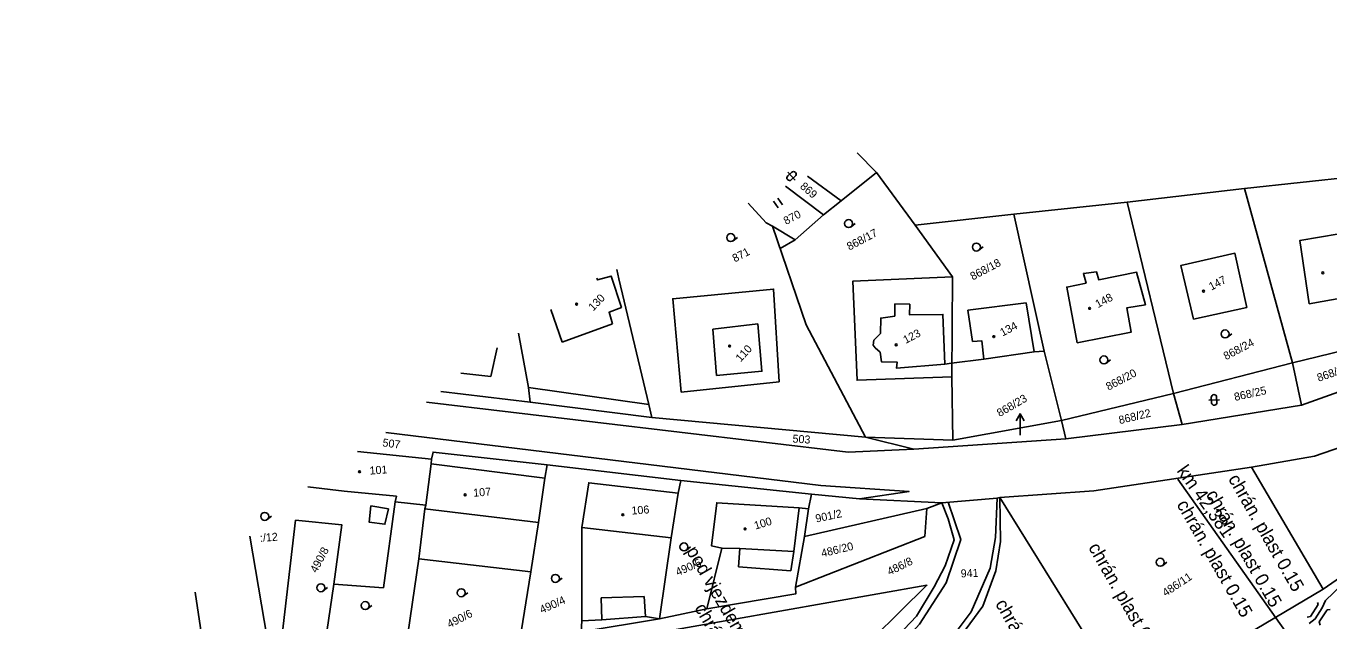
# Model space of a CAD drawing. Extents: x -514509 to -512782, y -1144610 to -1143439.
# Drawn here: x -513652.6 to -513408.3, y -1143676 to -1143564.4 of the extents above; entities that cross this region are included whole.
import ezdxf

# ---------------------------------------------------------------- set-up
doc = ezdxf.new("R2010")
doc.units = 0
for name, color, linetype in [('Vrstva 1', 7, 'Continuous'), ('Vrstva 10', 7, 'Continuous'), ('Vrstva 25', 7, 'Continuous'), ('Vrstva 61', 7, 'Continuous'), ('Vrstva 62', 7, 'Continuous'), ('Vrstva 8', 7, 'Continuous'), ('Vrstva 9', 7, 'Continuous')]:
    doc.layers.add(name, color=color, linetype=linetype)

msp = doc.modelspace()

# ---------------------------------------------------------------- linework, layer by layer
at = {"layer": 'Vrstva 1'}
msp.add_lwpolyline([(-513412.036, -1143676.539), (-513410.908, -1143675.642), (-513409.638, -1143673.559), (-513409.022, -1143672.206), (-513406.01, -1143669.345)], dxfattribs=at)
at = {"layer": 'Vrstva 10'}
msp.add_lwpolyline([(-513582.696, -1143761.24), (-513581.966, -1143752.218), (-513543.007, -1143722.265), (-513536.98, -1143726.125), (-513503.11, -1143701.59), (-513467.163, -1143704.368), (-513409.406, -1143670.068), (-513367.763, -1143641.182), (-513337.875, -1143622.14), (-513302.677, -1143606.244), (-513297.569, -1143595.846), (-513289.461, -1143596.696), (-513287.694, -1143584.666), (-513262.147, -1143588.316), (-513251.067, -1143584.844), (-513248.39, -1143579.25), (-513218.784, -1143572.229), (-513191.434, -1143567.629), (-513154.1, -1143564.42), (-513082.649, -1143574.448)], dxfattribs=at)
msp.add_lwpolyline([(-513582.696, -1143761.24), (-513581.966, -1143752.218), (-513543.007, -1143722.265), (-513536.98, -1143726.125), (-513503.11, -1143701.59), (-513467.163, -1143704.368), (-513409.406, -1143670.068), (-513367.763, -1143641.182), (-513337.875, -1143622.14), (-513302.677, -1143606.244), (-513297.569, -1143595.846), (-513289.461, -1143596.696), (-513287.694, -1143584.666), (-513262.147, -1143588.316), (-513251.067, -1143584.844), (-513248.39, -1143579.25), (-513218.784, -1143572.229), (-513191.434, -1143567.629), (-513154.1, -1143564.42), (-513082.649, -1143574.448)], dxfattribs=at)
for points in [[(-513313.028, -1143634.411), (-513303.623, -1143630.921), (-513298.925, -1143628.763), (-513296.747, -1143627.462), (-513295.945, -1143626.166), (-513295.554, -1143624.532), (-513295.924, -1143622.761), (-513296.628, -1143622.04), (-513297.564, -1143622.144), (-513299.651, -1143622.875), (-513306.089, -1143625.417), (-513313.165, -1143628.458), (-513321.801, -1143632.456), (-513331.249, -1143637.407), (-513340.422, -1143642.868), (-513349.401, -1143648.415), (-513353.369, -1143652.099), (-513356.695, -1143655.538), (-513359.416, -1143658.705), (-513362.379, -1143661.416), (-513365.213, -1143663.797), (-513369.131, -1143666.807), (-513372.727, -1143669.506), (-513383.146, -1143676.5), (-513393.468, -1143683.537), (-513398.042, -1143686.718), (-513405.384, -1143691.933), (-513410.151, -1143695.762), (-513415.154, -1143699.922), (-513418.131, -1143702.84), (-513423.071, -1143706.989), (-513430.088, -1143713.017)], [(-513435.79, -1143720.105), (-513422.696, -1143709.16), (-513412.424, -1143700.068), (-513405.215, -1143694.088), (-513397.354, -1143688.38), (-513386.063, -1143680.692), (-513374.141, -1143672.521), (-513366.016, -1143666.699), (-513361.881, -1143663.312), (-513358.552, -1143660.3), (-513355.953, -1143657.514), (-513352.811, -1143654.119), (-513350.492, -1143651.614), (-513348.384, -1143649.644), (-513345.759, -1143647.798), (-513339.616, -1143643.857), (-513326.377, -1143636.333), (-513315.497, -1143630.928), (-513306.602, -1143627.259), (-513301.474, -1143625.525)], [(-513411.988, -1143704.704), (-513402.55, -1143697.523), (-513392.088, -1143689.804), (-513385.47, -1143685.32), (-513382.766, -1143683.684), (-513373.999, -1143679.047), (-513366.674, -1143674.561), (-513360.563, -1143670.218), (-513355.795, -1143665.131), (-513348.391, -1143656.829), (-513341.216, -1143651.53), (-513334.333, -1143646.865), (-513323.242, -1143640.123), (-513316.692, -1143635.986), (-513314.355, -1143634.999)]]:
    msp.add_spline(points, degree=3, dxfattribs=at)
at = {"layer": 'Vrstva 25'}
msp.add_lwpolyline([(-513436.662, -1143649.403), (-513415.746, -1143679.07)], dxfattribs=at)
at = {"layer": 'Vrstva 61'}
for points in [[(-513412.442, -1143675.308), (-513411.824, -1143675.194), (-513410.36, -1143672.938)], [(-513410.36, -1143672.938), (-513410.463, -1143672.558)], [(-513408.699, -1143673.926), (-513410.157, -1143676.216), (-513410.015, -1143676.829)], [(-513408.097, -1143673.862), (-513408.699, -1143673.926)]]:
    msp.add_lwpolyline(points, dxfattribs=at)
at = {"layer": 'Vrstva 8'}
for p, q in [((-513496.813, -1143588.219), (-513493.199, -1143591.919)), ((-513506.131, -1143592.588), (-513499.789, -1143597.189)), ((-513503.084, -1143599.824), (-513510.199, -1143594.48)), ((-513424.194, -1143594.886), (-513415.173, -1143627.584)), ((-513512.666, -1143601.956), (-513508.41, -1143604.514)), ((-513489.755, -1143616.528), (-513486.929, -1143616.584)), ((-513476.067, -1143617.711), (-513465.107, -1143616.372)), ((-513465.107, -1143616.372), (-513463.62, -1143625.531)), ((-513552.076, -1143623.724), (-513554.237, -1143617.582)), ((-513542.69, -1143620.298), (-513552.076, -1143623.724)), ((-513523.833, -1143621.299), (-513515.396, -1143620.27)), ((-513415.173, -1143627.584), (-513413.496, -1143635.563)), ((-513558.398, -1143632.231), (-513535.869, -1143635.399)), ((-513458.472, -1143638.442), (-513457.653, -1143641.833)), ((-513576.62, -1143645.693), (-513590.455, -1143644.269)), ((-513576.63, -1143646.545), (-513555.337, -1143649.273)), ((-513583.419, -1143653.702), (-513577.671, -1143654.306)), ((-513584.673, -1143654.966), (-513587.964, -1143654.446)), ((-513577.832, -1143654.976), (-513556.52, -1143657.535)), ((-513548.403, -1143658.526), (-513531.65, -1143660.464)), ((-513508.339, -1143669.664), (-513506.675, -1143660.162)), ((-513518.81, -1143662.466), (-513508.658, -1143663.024)), ((-513519.01, -1143665.861), (-513509.226, -1143666.645)), ((-513544.797, -1143671.724), (-513536.698, -1143671.435)), ((-513544.681, -1143675.792), (-513544.797, -1143671.724)), ((-513536.698, -1143671.435), (-513536.469, -1143675.171)), ((-513536.469, -1143675.171), (-513544.681, -1143675.792)), ((-513481.481, -1143682.388), (-513475.438, -1143674.345))]:
    msp.add_line(p, q, dxfattribs=at)
for points in [[(-513485.907, -1143601.797), (-513493.199, -1143591.919), (-513499.789, -1143597.189), (-513503.084, -1143599.824), (-513508.41, -1143604.514), (-513511.234, -1143606.136)], [(-513403.286, -1143592.638), (-513424.194, -1143594.886), (-513446.168, -1143597.475), (-513467.416, -1143599.696), (-513485.907, -1143601.797), (-513478.935, -1143611.479), (-513479.065, -1143630.227), (-513478.852, -1143642.096), (-513458.472, -1143638.442), (-513437.507, -1143633.384), (-513415.173, -1143627.584), (-513393.849, -1143622.385)], [(-513478.852, -1143642.096), (-513495.247, -1143641.551), (-513506.339, -1143620.454), (-513512.666, -1143601.956), (-513513.883, -1143601.347), (-513517.242, -1143597.667)], [(-513435.839, -1143639.146), (-513437.507, -1143633.384), (-513446.168, -1143597.475)], [(-513458.472, -1143638.442), (-513461.724, -1143625.391), (-513467.416, -1143599.696)], [(-513422.854, -1143647.177), (-513411.055, -1143645.138), (-513373.068, -1143631.979), (-513339.412, -1143613.869), (-513313.432, -1143600.771), (-513322.783, -1143615.321)], [(-513535.285, -1143637.833), (-513535.869, -1143635.399), (-513541.458, -1143611.844), (-513541.863, -1143610.106)], [(-513545.612, -1143611.707), (-513545.479, -1143612.058), (-513542.91, -1143611.326), (-513540.978, -1143617.195), (-513543.31, -1143618.117), (-513542.69, -1143620.298)], [(-513479.065, -1143630.227), (-513496.818, -1143630.885), (-513497.619, -1143612.315), (-513478.935, -1143611.479)], [(-513461.724, -1143625.391), (-513463.62, -1143625.531), (-513473.039, -1143626.908), (-513479.133, -1143627.698), (-513480.352, -1143627.856), (-513489.442, -1143628.577), (-513489.322, -1143627.478), (-513492.233, -1143627.415), (-513492.464, -1143625.606), (-513493.402, -1143624.763), (-513493.781, -1143624.306), (-513493.679, -1143623.376), (-513492.425, -1143622.112), (-513492.366, -1143619.218), (-513489.749, -1143618.831), (-513489.755, -1143616.528)], [(-513486.929, -1143616.584), (-513486.98, -1143618.626), (-513480.705, -1143618.533), (-513480.352, -1143627.856)], [(-513473.039, -1143626.908), (-513473.435, -1143623.465), (-513475.164, -1143623.582), (-513476.067, -1143617.711)], [(-513558.107, -1143634.982), (-513558.398, -1143632.231), (-513560.254, -1143622.02)], [(-513515.396, -1143620.27), (-513514.656, -1143629.199), (-513523.151, -1143629.967), (-513523.833, -1143621.299)], [(-513571.078, -1143629.534), (-513565.481, -1143630.154), (-513564.294, -1143624.791)], [(-513577.56, -1143634.96), (-513498.476, -1143644.362), (-513486.158, -1143643.813), (-513457.653, -1143641.833), (-513435.839, -1143639.146), (-513413.496, -1143635.563), (-513391.444, -1143627.693)], [(-513486.158, -1143643.813), (-513495.247, -1143641.551), (-513535.285, -1143637.833), (-513558.107, -1143634.982), (-513574.85, -1143632.96)], [(-513496.375, -1143653.142), (-513487.048, -1143651.757), (-513503.632, -1143650.6), (-513585.141, -1143640.662)], [(-513578.968, -1143664.349), (-513577.832, -1143654.976), (-513577.671, -1143654.306), (-513576.63, -1143646.545), (-513576.62, -1143645.693), (-513576.299, -1143644.355), (-513554.883, -1143646.752), (-513529.843, -1143649.695), (-513505.36, -1143652.252), (-513496.375, -1143653.142), (-513480.942, -1143653.866), (-513470.559, -1143652.992)], [(-513557.986, -1143666.797), (-513556.52, -1143657.535), (-513555.337, -1143649.273), (-513554.883, -1143646.752)], [(-513470.031, -1143652.864), (-513452.408, -1143651.632), (-513422.854, -1143647.177), (-513409.406, -1143670.068)], [(-513583.129, -1143652.617), (-513592.979, -1143651.656), (-513599.758, -1143650.857)], [(-513548.39, -1143676.007), (-513548.403, -1143658.526), (-513547.116, -1143650.102), (-513530.363, -1143652.041)], [(-513529.843, -1143649.695), (-513530.363, -1143652.041), (-513531.65, -1143660.464), (-513533.864, -1143675.635), (-513536.469, -1143675.171)], [(-513594.93, -1143669.125), (-513585.611, -1143669.815), (-513583.419, -1143653.702), (-513583.129, -1143652.617)], [(-513492.629, -1143682.433), (-513485.641, -1143675.148), (-513482.364, -1143669.612), (-513480.295, -1143665.685), (-513478.632, -1143660.787), (-513479.735, -1143656.862), (-513480.942, -1143653.866), (-513483.718, -1143654.923), (-513484.135, -1143660.176), (-513508.339, -1143669.664), (-513508.312, -1143670.945), (-513525, -1143673.787), (-513533.864, -1143675.635), (-513548.533, -1143678.042)], [(-513525, -1143673.787), (-513522.146, -1143662.369), (-513524.075, -1143661.958), (-513523.103, -1143653.849), (-513507.676, -1143654.831), (-513505.927, -1143655.021)], [(-513483.718, -1143654.923), (-513506.675, -1143660.162), (-513505.927, -1143655.021), (-513505.36, -1143652.252)], [(-513479.738, -1143653.763), (-513477.339, -1143660.72), (-513480.136, -1143668.853), (-513485.123, -1143676.639), (-513491.478, -1143683.634), (-513495.386, -1143687.158)], [(-513446.005, -1143691.624), (-513470.031, -1143652.864), (-513469.93, -1143661.143), (-513470.8, -1143666.616), (-513473.257, -1143673.241), (-513480.547, -1143683.23), (-513486.741, -1143689.555), (-513493.388, -1143694.566), (-513487.156, -1143688.669), (-513481.481, -1143682.388)], [(-513475.438, -1143674.345), (-513471.857, -1143666.105), (-513470.874, -1143660.385), (-513470.559, -1143652.992), (-513470.031, -1143652.864)], [(-513587.964, -1143654.446), (-513588.296, -1143657.49), (-513585.337, -1143657.898), (-513584.673, -1143654.966)], [(-513509.226, -1143666.645), (-513508.658, -1143663.024), (-513507.676, -1143654.831)], [(-513605.792, -1143688.805), (-513602.071, -1143657.127), (-513593.426, -1143657.99), (-513594.93, -1143669.125), (-513597.533, -1143686.993)], [(-513605.792, -1143688.805), (-513610.633, -1143660.108)], [(-513522.146, -1143662.369), (-513518.81, -1143662.466), (-513519.01, -1143665.861)], [(-513581.863, -1143684.07), (-513578.968, -1143664.349), (-513557.986, -1143666.797), (-513560.068, -1143680.017)], [(-513661.135, -1143698.528), (-513647.306, -1143695.968), (-513617.922, -1143690.733), (-513620.897, -1143670.627)], [(-513538.877, -1143679.071), (-513483.704, -1143669.334), (-513513.863, -1143699.065), (-513532.594, -1143713.255)], [(-513544.681, -1143675.792), (-513548.39, -1143676.007), (-513548.533, -1143678.042)]]:
    msp.add_lwpolyline(points, dxfattribs=at)
for points in [[(-513412.086, -1143616.531), (-513413.788, -1143604.626), (-513402.772, -1143602.781), (-513401.231, -1143614.588)], [(-513433.769, -1143619.397), (-513436.1, -1143609.318), (-513425.983, -1143607.059), (-513423.747, -1143617.216)], [(-513455.543, -1143623.876), (-513457.487, -1143613.402), (-513453.888, -1143612.667), (-513454.374, -1143610.837), (-513451.937, -1143610.521), (-513451.498, -1143612.006), (-513444.395, -1143610.614), (-513442.745, -1143616.716), (-513446.24, -1143617.289), (-513445.454, -1143621.871)], [(-513529.759, -1143633.104), (-513531.36, -1143615.579), (-513512.453, -1143613.769), (-513511.438, -1143631.162)]]:
    msp.add_lwpolyline(points, close=True, dxfattribs=at)
at = {"layer": 'Vrstva 9'}
for p, q in [((-513509.06, -1143591.863), (-513509.807, -1143592.528)), ((-513509.767, -1143591.825), (-513508.436, -1143593.316)), ((-513508.395, -1143592.611), (-513509.142, -1143593.276)), ((-513512.471, -1143597.274), (-513511.631, -1143598.517)), ((-513510.803, -1143597.957), (-513511.642, -1143596.713)), ((-513497.946, -1143602.068), (-513497.155, -1143601.458)), ((-513520.04, -1143604.708), (-513519.249, -1143604.098)), ((-513473.982, -1143606.474), (-513473.191, -1143605.864)), ((-513427.346, -1143622.774), (-513426.555, -1143622.164)), ((-513450.084, -1143627.663), (-513449.293, -1143627.053)), ((-513430.874, -1143634.612), (-513428.876, -1143634.517)), ((-513430.399, -1143634.087), (-513430.352, -1143635.086)), ((-513429.399, -1143634.041), (-513429.353, -1143635.04)), ((-513466.998, -1143638.459), (-513466.248, -1143637.159)), ((-513607.405, -1143657.013), (-513606.614, -1143656.403)), ((-513528.81, -1143662.745), (-513528.019, -1143662.135)), ((-513439.52, -1143665.61), (-513438.729, -1143665)), ((-513552.915, -1143668.635), (-513552.124, -1143668.025)), ((-513596.88, -1143670.386), (-513596.089, -1143669.776)), ((-513570.569, -1143671.341), (-513569.778, -1143670.731)), ((-513588.563, -1143673.729), (-513587.772, -1143673.119))]:
    msp.add_line(p, q, dxfattribs=at)
msp.add_lwpolyline([(-513466.248, -1143641.159), (-513466.248, -1143637.159), (-513465.498, -1143638.459)], dxfattribs=at)
for centre, radius in [((-513498.405, -1143601.474), 0.75), ((-513520.499, -1143604.114), 0.75), ((-513474.441, -1143605.88), 0.75), ((-513409.508, -1143610.714), 0.175), ((-513431.861, -1143614.149), 0.175), ((-513549.391, -1143616.593), 0.175), ((-513453.212, -1143617.388), 0.175), ((-513427.805, -1143622.18), 0.75), ((-513520.704, -1143624.451), 0.175), ((-513489.468, -1143624.235), 0.175), ((-513471.171, -1143622.685), 0.175), ((-513450.543, -1143627.069), 0.75), ((-513590.08, -1143648.028), 0.175), ((-513570.3, -1143652.387), 0.175), ((-513607.864, -1143656.419), 0.75), ((-513540.742, -1143656.094), 0.175), ((-513517.812, -1143658.77), 0.175), ((-513529.269, -1143662.151), 0.75), ((-513439.979, -1143665.016), 0.75), ((-513553.374, -1143668.041), 0.75), ((-513597.339, -1143669.792), 0.75), ((-513571.028, -1143670.747), 0.75), ((-513589.022, -1143673.135), 0.75)]:
    msp.add_circle(centre, radius, dxfattribs=at)
for centre, start, end in [((-513509.475, -1143592.901), 131.65197, 311.65197), ((-513508.728, -1143592.237), 311.65197, 131.65197), ((-513429.899, -1143634.064), 2.64079, 182.64079), ((-513429.853, -1143635.063), 182.64079, 2.64079)]:
    msp.add_arc(centre, 0.5, start, end, dxfattribs=at)

# ---------------------------------------------------------------- texts
at = {"layer": 'Vrstva 25'}
msp.add_text('km 42,381', height=2.5, rotation=305.18441, dxfattribs=at).set_placement((-513436.971, -1143647.883))
at = {"layer": 'Vrstva 62'}
for s, rotation, p in [('chrán. plast 0.15', 299.82808, (-513427.319, -1143649.358)), ('chrán. plast 0.15', 299.82808, (-513436.979, -1143654.178)), ('chrán. plast 0.15', 299.82808, (-513431.493, -1143652.284)), ('pod vjezdem protlak', 300.1817, (-513528.936, -1143662.875)), ('chrán. plast 0.15', 299.82808, (-513453.54, -1143662.233)), ('chrán. plast 0.11', 300.1817, (-513527.369, -1143673.597)), ('chrán. plast 0.15', 299.82808, (-513470.984, -1143672.803))]:
    msp.add_text(s, height=2.5, rotation=rotation, dxfattribs=at).set_placement(p)
at = {"layer": 'Vrstva 9'}
for s, rotation, p in [('869', 319.48854, (-513507.624, -1143594.705)), ('870', 27.81912, (-513510.124, -1143601.759)), ('868/17', 27.81912, (-513498.247, -1143606.565)), ('871', 27.81912, (-513519.708, -1143608.785)), ('868/18', 27.81912, (-513475.121, -1143612.158)), ('147', 27.81912, (-513430.385, -1143614.064)), ('130', 45.90392, (-513546.275, -1143617.979)), ('148', 27.81912, (-513451.661, -1143617.355)), ('134', 27.81912, (-513469.529, -1143622.681)), ('123', 27.81912, (-513487.691, -1143624.069)), ('110', 47.17304, (-513518.647, -1143627.542)), ('868/24', 27.81912, (-513427.639, -1143627.129)), ('868/20', 27.81912, (-513449.675, -1143632.845)), ('868/21', 19.29068, (-513410.277, -1143631.178)), ('868/25', 12.4873, (-513425.953, -1143634.767)), ('868/23', 30.20243, (-513470.073, -1143637.798)), ('868/22', 13.64693, (-513447.573, -1143639.115)), ('507', 352.40674, (-513585.851, -1143643.269)), ('503', 356.35765, (-513508.947, -1143642.555)), ('101', 4.36014, (-513588.144, -1143648.586)), ('107', 4.36014, (-513568.724, -1143652.74)), ('106', 4.36014, (-513539.051, -1143656.088)), ('901/2', 11.99689, (-513504.449, -1143657.577)), ('100', 16.91798, (-513515.854, -1143658.906)), (':/12', 4.36014, (-513608.7, -1143661.211)), ('486/20', 13.54481, (-513503.356, -1143664.088)), ('490/8', 61.90523, (-513598.132, -1143667.113)), ('490/5', 23.512, (-513530.433, -1143667.627)), ('486/8', 26.25571, (-513490.716, -1143667.53)), ('941', 2.24426, (-513477.357, -1143667.874)), ('486/11', 33.84112, (-513438.948, -1143671.516)), ('490/4', 24.00788, (-513555.913, -1143674.684)), ('490/6', 26.99066, (-513573.217, -1143677.403))]:
    msp.add_text(s, height=1.5, rotation=rotation, dxfattribs=at).set_placement(p)

doc.saveas('drawing.dxf')
